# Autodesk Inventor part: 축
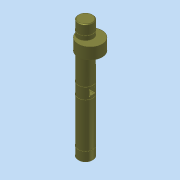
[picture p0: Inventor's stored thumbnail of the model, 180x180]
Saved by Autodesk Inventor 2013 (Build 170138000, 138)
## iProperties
Company: 한국ATC센터
Created: 2015-04
Part Number: 축
Document SubType Name: Modeling
Designer: KYOUNG IL JANG
Density: 7.85 g/cm^3
Material: 강철
Mass: 606.905 g
Surface Area: 163.755 cm^2
Volume: 77.3127 cm^3
Author: KYOUNG IL JANG
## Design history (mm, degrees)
sketch "스케치1"
  geometry: C1 r 11 at (0, 0); 1 further point
  constraints: 1 centre point, 1 coincident
  dimensions: "d0" = 22 diameter of C1
extrude "돌출1" new body sketch "스케치1" stored distance "d1" = 180; taper "d2" = 0 deg
sketch "스케치2"
  geometry: L1 (-10.247, -4)-(10.247, -4); L2 (-10.247, 4)-(10.247, 4); A1 r 11 centre (0, 0) between (-10.247, -4) and (10.247, -4) reference; 1 further point
  constraints: 4 end point, 4 point on circle, 2 parallel, 1 horizontal
  dimensions: "d3" = 8 distance between parallel lines of L2 L1
extrude "돌출2" cut sketch "스케치2" stored distance "d4" = 8; taper "d5" = 0 deg
sketch "스케치3"
  geometry: 5 further points
hole "구멍1" sketch "스케치3" at (-4, 4), (4, 4), (4, -4), (-4, -4) diameter "d6" = 2; stored, may be unused: countersink angle "d10" = 90 deg, drill point angle "d12" = 118 deg; dims "d7" = 6, "d8" = 4, "d9" = 2, "d11" = 8
chamfer "모따기1" distance "d13" = 1; stored, may be unused: second distance "d14" = 2, angle "d15" = 45 deg
sketch "스케치4"
  geometry: L1 (-10, 9)-(-11, 9); L2 (-11, 9)-(-11, 7.8); L3 (-11, 7.8)-(-10, 7.8); L4 (-10, 7.8)-(-10, 9); L5 (-10, 90)-(10, 90) reference; L6 (0, -15)-(0, 90) reference; L7 (-10, 74.8)-(-11, 74.8); L8 (-11, 74.8)-(-11, 76); L9 (-11, 76)-(-10, 76); L10 (-10, 76)-(-10, 74.8); 1 further point
  constraints: 16 end point, 4 parallel, 2 equal length, 2 horizontal, 2 perpendicular, 1 collinear
  dimensions: "d16" = 7.8 distance from line of L3 point (0, 0); "d17" = 82.2 distance between parallel lines of L3 L5 (derived); "d18" = 11 distance from line of point (0, 0) L2; "d19" = 1 distance of L2.end L3.end; "d20" = 1.2 distance of L1.end L2.end; "d27" = 14 distance between parallel lines of L5 L9
revolve "회전1" sketch "스케치4" stored, may be unused: angle "d21" = 90 deg
sketch "스케치5"
  geometry: L1 (11, 52)-(-7, 52); L2 (-7, 52)-(-7, 69); L3 (-7, 69)-(11, 69); L4 (11, 69)-(11, 52); 1 further point
  constraints: 8 end point, 2 parallel, 1 horizontal, 1 perpendicular
  dimensions: "d22" = 17 distance of L3.end L1.start; "d23" = 36 diameter of L4 L2; "d24" = 7 horizontal distance of L2.end point (0, 0); "d25" = 52 distance from line of L1 point (0, 0)
revolve "회전2" sketch "스케치5" stored, may be unused: angle "d26" = 90 deg
node "솔리드1"
mirror "대칭1"
mirror "대칭2"
